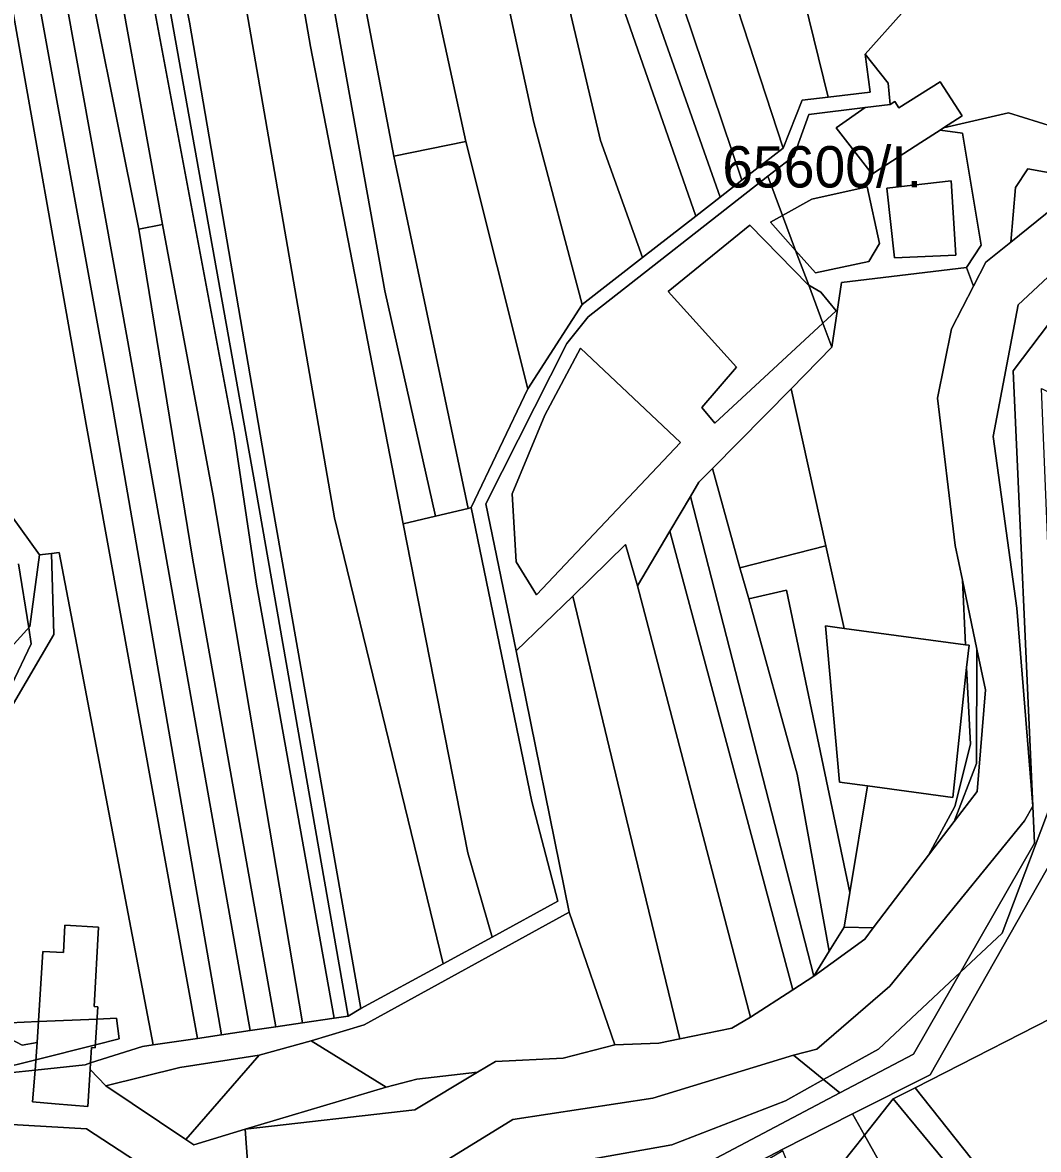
# Model space of a CAD drawing. Extents: x -502026 to -497664, y -1143484 to -1138019.
# Drawn here: x -499256.7 to -499060, y -1140803.4 to -1140585.2 of the extents above; entities that cross this region are included whole.
import ezdxf

# ---------------------------------------------------------------- set-up
doc = ezdxf.new("R2010")
doc.units = 0
for name, color, linetype in [('25', 7, 'Continuous'), ('37', 7, 'Continuous'), ('43', 7, 'Continuous'), ('49', 7, 'Continuous'), ('55', 7, 'Continuous'), ('62', 7, 'Continuous'), ('7', 7, 'Continuous')]:
    doc.layers.add(name, color=color, linetype=linetype)

msp = doc.modelspace()

# ---------------------------------------------------------------- linework, layer by layer
at = {"layer": '25'}
for points in [[(-499046.23, -1140577.07), (-499044.44, -1140577.08), (-499038.84, -1140582.85), (-499039.7, -1140583.71), (-499053.55, -1140597.58), (-499047.59, -1140603.5), (-499051.26, -1140607.19), (-499065.8, -1140602.64), (-499078.37, -1140605.55), (-499074.79, -1140603.26), (-499079.03, -1140596.64), (-499087.03, -1140601.69), (-499087.82, -1140600.44), (-499088.69, -1140601.02), (-499089.09, -1140596.91), (-499093.56, -1140591.31), (-499086.55, -1140583.39), (-499081.37, -1140581.73), (-499069.49, -1140582.91), (-499066.15, -1140581.28), (-499057.06, -1140576.83)], [(-499101.17, -1140686.53), (-499117.79, -1140690.8), (-499123.13, -1140671.52), (-499107.9, -1140656.08)], [(-499097.65, -1140702.49), (-499101.24, -1140702), (-499098.5, -1140732.28), (-499093.13, -1140733.02), (-499096.54, -1140753.64), (-499108.79, -1140695.11), (-499116.1, -1140696.77), (-499117.79, -1140690.8), (-499101.17, -1140686.53)], [(-499096.54, -1140753.64), (-499097.65, -1140760.34), (-499100.52, -1140765.03), (-499106.71, -1140730.74), (-499116.1, -1140696.77), (-499108.79, -1140695.11)]]:
    msp.add_lwpolyline(points, close=True, dxfattribs=at)
at = {"layer": '37'}
for points in [[(-499142.03, -1140783.15), (-499152.04, -1140785.71), (-499165.14, -1140786.36), (-499168.58, -1140788.47), (-499180.35, -1140789.82), (-499186.28, -1140791.32), (-499200.84, -1140782.35), (-499190.58, -1140779.27), (-499150.86, -1140757.46)], [(-499027.17, -1140859.16), (-499039.41, -1140846.13), (-499055.84, -1140826.78), (-499083.85, -1140791.45), (-499051.81, -1140775.1), (-499049.74, -1140796.19), (-499037.55, -1140844.52), (-499031.03, -1140843.42)], [(-499093.69, -1140800.62), (-499104.95, -1140814.88), (-499109.51, -1140803.7), (-499127.89, -1140814.52), (-499149.4, -1140825.3), (-499162.04, -1140835.16), (-499163.96, -1140837.47), (-499165.34, -1140840.32), (-499168.31, -1140844.22), (-499168.31, -1140845.8), (-499179.89, -1140858.73), (-499202.02, -1140881.64), (-499183.66, -1140858.73), (-499166.49, -1140833.21), (-499109.48, -1140803.35), (-499095.98, -1140796.53)], [(-499074.18, -1141090.69), (-499085.94, -1141005.64), (-499111.86, -1140862.39), (-499119.95, -1140833.05), (-499102.17, -1140821.68), (-499104.95, -1140814.88), (-499093.69, -1140800.62), (-499076.01, -1140832.19), (-499068.35, -1140891.61), (-499073.21, -1140904.83), (-499057.38, -1140940.7), (-499042.46, -1140998.31), (-499052.02, -1141001.86), (-499061.09, -1141020.67), (-499058.7, -1141085.37)]]:
    msp.add_lwpolyline(points, close=True, dxfattribs=at)
at = {"layer": '43'}
for points in [[(-499277.06, -1140748.76), (-499311.03, -1140789.86), (-499304.44, -1140768.17), (-499278.12, -1140737.7), (-499277.15, -1140726.28), (-499255.28, -1140702.14), (-499253.41, -1140688.26), (-499251.1, -1140688), (-499250.63, -1140703.66)], [(-499098.45, -1140792.47), (-499169.08, -1140829.79), (-499220.72, -1140841.83), (-499256.21, -1140836.16), (-499277.72, -1140829.32), (-499287.7, -1140819.38), (-499306.66, -1140814.44), (-499352.42, -1140810.64), (-499336.3, -1140807.98), (-499328.65, -1140806.13), (-499324.82, -1140798.07), (-499318.22, -1140791.11), (-499315.45, -1140795.96), (-499302.12, -1140802.04), (-499267.8, -1140798.07), (-499244.32, -1140799.43), (-499230, -1140808.8), (-499223.13, -1140810.06), (-499213.06, -1140806.58), (-499212.54, -1140813.69), (-499178.21, -1140807.73), (-499161.8, -1140797.63), (-499134.65, -1140793.45), (-499107.41, -1140785.15)]]:
    msp.add_lwpolyline(points, close=True, dxfattribs=at)
at = {"layer": '49'}
for points in [[(-499088.69, -1140601.02), (-499093.53, -1140601.61), (-499104.46, -1140602.95), (-499107.34, -1140611.05), (-499112.42, -1140614.89), (-499147.18, -1140642.14), (-499151.34, -1140647.33), (-499167, -1140678.36), (-499161.11, -1140706.87), (-499150.86, -1140757.46), (-499190.58, -1140779.27), (-499200.84, -1140782.35), (-499210.91, -1140785.18), (-499226.23, -1140787.52), (-499240.55, -1140791.12), (-499243.62, -1140787.96), (-499243.54, -1140786.63), (-499233.45, -1140783.49), (-499231.38, -1140783.18), (-499222.82, -1140781.91), (-499218.19, -1140781.23), (-499212.6, -1140780.4), (-499207.66, -1140779.67), (-499202.47, -1140778.9), (-499196.38, -1140778), (-499193.66, -1140777.6), (-499191.2, -1140776.13), (-499175.25, -1140767.44), (-499165.77, -1140762.27), (-499153.04, -1140755.33), (-499158.1, -1140736.04), (-499169.83, -1140679.11), (-499158.84, -1140656.08), (-499148.34, -1140639.76), (-499136.68, -1140630.69), (-499126.34, -1140622.65), (-499121.6, -1140618.96), (-499117.43, -1140615.72), (-499109.46, -1140609.52), (-499105.73, -1140600.19), (-499100.72, -1140599.59), (-499092.59, -1140598.62), (-499093.56, -1140591.31), (-499089.09, -1140596.91)], [(-499075.98, -1140630.21), (-499087.86, -1140630.73), (-499089.39, -1140617.21), (-499076.89, -1140615.85)], [(-499107.02, -1140629.29), (-499109.55, -1140622.53), (-499103.88, -1140619.37), (-499093.18, -1140616.99), (-499090.81, -1140627.99), (-499092.85, -1140631.42), (-499103.15, -1140633.62)], [(-499104.48, -1140636.06), (-499101.74, -1140643.37), (-499122.67, -1140662.76), (-499125.2, -1140659.73), (-499118.48, -1140651.93), (-499131.72, -1140637.28), (-499115.91, -1140624.38), (-499104.62, -1140635.97)], [(-499107.02, -1140629.29), (-499111.9, -1140623.84), (-499109.55, -1140622.53)], [(-499101.74, -1140643.37), (-499104.48, -1140636.06), (-499102.16, -1140637.4), (-499099.19, -1140641.01)], [(-499129.28, -1140666.5), (-499157.22, -1140695.98), (-499161.12, -1140689.62), (-499161.88, -1140676.45), (-499155.56, -1140661.22), (-499148.66, -1140648.25)]]:
    msp.add_lwpolyline(points, close=True, dxfattribs=at)
for points in [[(-499213.06, -1140806.58), (-499213.58, -1140799.48), (-499180.73, -1140795.76), (-499168.58, -1140788.47), (-499165.14, -1140786.36), (-499152.04, -1140785.71), (-499142.03, -1140783.15), (-499133.53, -1140782.8), (-499129.46, -1140781.97), (-499119.38, -1140779.92), (-499115.76, -1140777.81), (-499107.58, -1140772.51), (-499103.47, -1140769.84), (-499093.62, -1140762.66), (-499091.98, -1140760.5), (-499081.3, -1140746.44), (-499076.35, -1140739.92), (-499071.9, -1140734.07), (-499070.28, -1140714.4), (-499071.93, -1140706.5), (-499074.73, -1140693.14), (-499076.12, -1140686.47), (-499079.52, -1140657.94), (-499076.87, -1140644.51), (-499072.58, -1140636.22), (-499070.17, -1140631.57), (-499065.36, -1140627.7), (-499056.95, -1140620.92)], [(-499052.36, -1140629.03), (-499063.95, -1140639.83), (-499068.76, -1140665.31), (-499064.16, -1140698.58), (-499061.08, -1140736.96), (-499062.7, -1140739.8), (-499088.79, -1140771.82), (-499102.91, -1140783.99), (-499107.41, -1140785.15), (-499134.65, -1140793.45), (-499161.8, -1140797.63), (-499178.21, -1140807.73)], [(-499264.63, -1140672.68), (-499253.41, -1140688.26), (-499255.28, -1140702.14), (-499277.15, -1140726.28)], [(-499299.02, -1140792.7), (-499254.28, -1140788.04), (-499254.78, -1140794.22), (-499250.4, -1140794.57), (-499244.07, -1140795.09), (-499243.62, -1140787.96), (-499240.55, -1140791.12), (-499225.11, -1140801.48), (-499223.53, -1140802.54), (-499213.58, -1140799.48), (-499213.06, -1140806.58)], [(-499230, -1140808.8), (-499244.32, -1140799.43), (-499267.8, -1140798.07)]]:
    msp.add_lwpolyline(points, dxfattribs=at)
at = {"layer": '55'}
for points in [[(-499078.37, -1140605.55), (-499079.04, -1140605.98), (-499082.8, -1140608.39), (-499091.53, -1140614.08), (-499092.22, -1140614.53), (-499099.16, -1140605.57), (-499093.53, -1140601.61), (-499088.69, -1140601.02), (-499087.82, -1140600.44), (-499087.03, -1140601.69), (-499079.03, -1140596.64), (-499074.79, -1140603.26)], [(-499079.04, -1140605.98), (-499074.68, -1140606.61), (-499071.1, -1140628.29), (-499073.93, -1140632.6), (-499098.12, -1140635.51), (-499099.98, -1140648.05), (-499101.74, -1140643.37), (-499099.19, -1140641.01), (-499102.16, -1140637.4), (-499104.48, -1140636.06), (-499107.02, -1140629.29), (-499103.15, -1140633.62), (-499092.85, -1140631.42), (-499090.81, -1140627.99), (-499093.18, -1140616.99), (-499103.88, -1140619.37), (-499109.55, -1140622.53), (-499112.42, -1140614.89), (-499107.34, -1140611.05), (-499104.46, -1140602.95), (-499093.53, -1140601.61), (-499099.16, -1140605.57), (-499092.22, -1140614.53), (-499091.53, -1140614.08), (-499082.8, -1140608.39)], [(-499051.26, -1140607.19), (-499047.02, -1140608.51), (-499038.79, -1140615.12), (-499050.8, -1140618.95), (-499053.11, -1140615.08), (-499062.07, -1140613.51), (-499064.46, -1140617.09), (-499065.36, -1140627.7), (-499070.17, -1140631.57), (-499072.58, -1140636.22), (-499073.93, -1140632.6), (-499071.1, -1140628.29), (-499074.68, -1140606.61), (-499079.04, -1140605.98), (-499078.37, -1140605.55), (-499065.8, -1140602.64)], [(-499050.8, -1140618.95), (-499056.95, -1140620.92), (-499065.36, -1140627.7), (-499064.46, -1140617.09), (-499062.07, -1140613.51), (-499053.11, -1140615.08)], [(-499109.55, -1140622.53), (-499111.9, -1140623.84), (-499107.02, -1140629.29), (-499104.48, -1140636.06), (-499104.62, -1140635.97), (-499115.91, -1140624.38), (-499131.72, -1140637.28), (-499118.48, -1140651.93), (-499125.2, -1140659.73), (-499122.67, -1140662.76), (-499101.74, -1140643.37), (-499099.98, -1140648.05), (-499107.9, -1140656.08), (-499123.13, -1140671.52), (-499125.73, -1140674.16), (-499127.4, -1140676.97), (-499131.38, -1140683.68), (-499137.65, -1140694.23), (-499139.97, -1140686.27), (-499150.13, -1140696.23), (-499161.11, -1140706.87), (-499167, -1140678.36), (-499151.34, -1140647.33), (-499147.18, -1140642.14), (-499112.42, -1140614.89)], [(-499075.98, -1140630.21), (-499076.89, -1140615.85), (-499089.39, -1140617.21), (-499087.86, -1140630.73)], [(-499061.08, -1140736.96), (-499064.16, -1140698.58), (-499068.76, -1140665.31), (-499063.95, -1140639.83), (-499052.36, -1140629.03), (-499045.77, -1140627.37), (-499064.92, -1140652.65)], [(-499072.58, -1140636.22), (-499076.87, -1140644.51), (-499079.52, -1140657.94), (-499076.12, -1140686.47), (-499074.73, -1140693.14), (-499074.12, -1140705.68), (-499097.65, -1140702.49), (-499101.17, -1140686.53), (-499107.9, -1140656.08), (-499099.98, -1140648.05), (-499098.12, -1140635.51), (-499073.93, -1140632.6)], [(-499129.28, -1140666.5), (-499148.66, -1140648.25), (-499155.56, -1140661.22), (-499161.88, -1140676.45), (-499161.12, -1140689.62), (-499157.22, -1140695.98)], [(-499020.1, -1140675.56), (-499029, -1140688.61), (-499033.93, -1140693.11), (-499030.81, -1140719.88), (-499035.84, -1140743.39), (-499034.62, -1140755.24), (-499032.97, -1140765.49), (-499051.81, -1140775.1), (-499083.85, -1140791.45), (-499088.14, -1140793.58), (-499093.69, -1140800.62), (-499095.98, -1140796.53), (-499080.97, -1140788.98), (-499055.8, -1140744.6), (-499059.42, -1140656.04)], [(-499231.38, -1140783.18), (-499233.45, -1140783.49), (-499243.54, -1140786.63), (-499243.35, -1140783.68), (-499242.62, -1140783.74), (-499242.09, -1140775.8), (-499242.86, -1140775.72), (-499242.02, -1140760.36), (-499248.5, -1140759.99), (-499248.79, -1140765.28), (-499252.74, -1140765.06), (-499253.84, -1140782.67), (-499256.76, -1140783.21), (-499267.22, -1140777.72), (-499277.06, -1140748.76), (-499250.63, -1140703.66), (-499251.1, -1140688), (-499249.58, -1140687.83), (-499246.17, -1140705.68)], [(-499071.93, -1140706.5), (-499071.99, -1140728.66), (-499076.35, -1140739.92), (-499081.3, -1140746.44), (-499076.18, -1140737), (-499073.19, -1140724.92), (-499073.91, -1140710.05), (-499073.45, -1140705.77), (-499074.12, -1140705.68), (-499074.73, -1140693.14)], [(-499097.65, -1140702.49), (-499074.12, -1140705.68), (-499073.45, -1140705.77), (-499073.91, -1140710.05), (-499076.61, -1140735.28), (-499093.13, -1140733.02), (-499098.5, -1140732.28), (-499101.24, -1140702)], [(-499076.35, -1140739.92), (-499071.99, -1140728.66), (-499071.93, -1140706.5), (-499070.28, -1140714.4), (-499071.9, -1140734.07)], [(-499081.3, -1140746.44), (-499091.98, -1140760.5), (-499097.65, -1140760.34), (-499096.54, -1140753.64), (-499093.13, -1140733.02), (-499076.61, -1140735.28), (-499073.91, -1140710.05), (-499073.19, -1140724.92), (-499076.18, -1140737)], [(-499098.45, -1140792.47), (-499107.41, -1140785.15), (-499102.91, -1140783.99), (-499088.79, -1140771.82), (-499062.7, -1140739.8), (-499061.08, -1140736.96), (-499060.76, -1140744.08), (-499084.18, -1140784.93)], [(-499253.84, -1140782.67), (-499254.28, -1140788.04), (-499299.02, -1140792.7), (-499311.03, -1140789.86), (-499277.06, -1140748.76), (-499267.22, -1140777.72), (-499256.76, -1140783.21)], [(-499243.54, -1140786.63), (-499244.57, -1140787.02), (-499250.02, -1140787.59), (-499254.28, -1140788.04), (-499253.84, -1140782.67), (-499252.74, -1140765.06), (-499248.79, -1140765.28), (-499248.5, -1140759.99), (-499242.02, -1140760.36), (-499242.86, -1140775.72), (-499242.09, -1140775.8), (-499242.62, -1140783.74), (-499243.35, -1140783.68)], [(-499091.98, -1140760.5), (-499093.62, -1140762.66), (-499103.47, -1140769.84), (-499100.52, -1140765.03), (-499097.65, -1140760.34)], [(-499186.28, -1140791.32), (-499213.58, -1140799.48), (-499223.53, -1140802.54), (-499225.11, -1140801.48), (-499210.91, -1140785.18), (-499200.84, -1140782.35)], [(-499225.11, -1140801.48), (-499240.55, -1140791.12), (-499226.23, -1140787.52), (-499210.91, -1140785.18)], [(-499243.62, -1140787.96), (-499244.07, -1140795.09), (-499250.4, -1140794.57), (-499254.78, -1140794.22), (-499254.28, -1140788.04), (-499250.02, -1140787.59), (-499244.57, -1140787.02), (-499243.54, -1140786.63)], [(-499213.58, -1140799.48), (-499186.28, -1140791.32), (-499180.35, -1140789.82), (-499168.58, -1140788.47), (-499180.73, -1140795.76)], [(-499027.17, -1140859.16), (-499026.07, -1140862.91), (-499030.49, -1140860.96), (-499059.43, -1140828.31), (-499088.14, -1140793.58), (-499083.85, -1140791.45), (-499055.84, -1140826.78), (-499039.41, -1140846.13)], [(-499026.07, -1140862.91), (-499025.31, -1140901.92), (-499045.76, -1140905.71), (-499036.36, -1140939.98), (-499029.76, -1140973.78), (-499028.12, -1140987.18), (-499023, -1141004.29), (-499026.05, -1141018.97), (-499027.79, -1141042.52), (-499029.21, -1141087.84), (-499073.37, -1141096.58), (-499074.18, -1141090.69), (-499058.7, -1141085.37), (-499061.09, -1141020.67), (-499052.02, -1141001.86), (-499042.46, -1140998.31), (-499057.38, -1140940.7), (-499073.21, -1140904.83), (-499068.35, -1140891.61), (-499076.01, -1140832.19), (-499093.69, -1140800.62), (-499088.14, -1140793.58), (-499059.43, -1140828.31), (-499030.49, -1140860.96)]]:
    msp.add_lwpolyline(points, close=True, dxfattribs=at)
for points in [[(-499169.08, -1140829.79), (-499098.45, -1140792.47), (-499084.18, -1140784.93), (-499060.76, -1140744.08), (-499061.08, -1140736.96), (-499064.92, -1140652.65), (-499045.77, -1140627.37)], [(-499055.8, -1140744.6), (-499080.97, -1140788.98), (-499095.98, -1140796.53), (-499109.48, -1140803.35), (-499166.49, -1140833.21)]]:
    msp.add_lwpolyline(points, dxfattribs=at)
at = {"layer": '62'}
for points in [[(-499266.5, -1140729.5), (-499255, -1140705.5), (-499255.5, -1140702.38), (-499257.5, -1140690)], [(-499257.5, -1140690), (-499255.5, -1140702.38), (-499255, -1140705.5), (-499266.5, -1140729.5)], [(-499178.5, -1140811), (-499131, -1140802.5), (-499109, -1140794), (-499101.61, -1140789.89), (-499091, -1140784), (-499075.1, -1140769.09), (-499067, -1140761.5), (-499056.27, -1140733.02)], [(-499056.27, -1140733.02), (-499067, -1140761.5), (-499075.1, -1140769.09), (-499091, -1140784), (-499101.61, -1140789.89), (-499109, -1140794), (-499131, -1140802.5), (-499178.5, -1140811)], [(-499262, -1140788), (-499254.12, -1140786.03), (-499242.58, -1140783.14), (-499238, -1140782), (-499238.5, -1140778), (-499242.25, -1140778.16), (-499253.59, -1140778.64), (-499262, -1140779)], [(-499262, -1140779), (-499253.59, -1140778.64), (-499242.25, -1140778.16), (-499238.5, -1140778), (-499238, -1140782), (-499242.58, -1140783.14), (-499254.12, -1140786.03), (-499262, -1140788)]]:
    msp.add_lwpolyline(points, dxfattribs=at)
at = {"layer": '7'}
for points in [[(-499086.55, -1140583.39), (-499093.56, -1140591.31), (-499092.59, -1140598.62), (-499100.72, -1140599.59), (-499129.23, -1140483.41), (-499114.75, -1140475.43), (-499108.4, -1140504.75), (-499093.32, -1140556.79)], [(-499100.72, -1140599.59), (-499105.73, -1140600.19), (-499109.46, -1140609.52), (-499125.99, -1140558.72), (-499133.51, -1140529.07), (-499142.57, -1140490.76), (-499129.23, -1140483.41)], [(-499109.46, -1140609.52), (-499117.43, -1140615.72), (-499130.6, -1140576.56), (-499141.21, -1140536.53), (-499150.34, -1140495.5), (-499142.57, -1140490.76), (-499133.51, -1140529.07), (-499125.99, -1140558.72)], [(-499117.43, -1140615.72), (-499121.6, -1140618.96), (-499136.08, -1140577.94), (-499147.66, -1140536.99), (-499155.56, -1140498.69), (-499150.34, -1140495.5), (-499141.21, -1140536.53), (-499130.6, -1140576.56)], [(-499121.6, -1140618.96), (-499126.34, -1140622.65), (-499140.99, -1140580.59), (-499154.21, -1140533), (-499159.55, -1140503.7), (-499159.98, -1140501.39), (-499155.56, -1140498.69), (-499147.66, -1140536.99), (-499136.08, -1140577.94)], [(-499126.34, -1140622.65), (-499136.68, -1140630.69), (-499144.8, -1140608), (-499168.02, -1140509.43), (-499159.55, -1140503.7), (-499154.21, -1140533), (-499140.99, -1140580.59)], [(-499168.02, -1140509.43), (-499144.8, -1140608), (-499136.68, -1140630.69), (-499148.34, -1140639.76), (-499157.71, -1140604.5), (-499177.54, -1140513.37), (-499170.64, -1140508.17)], [(-499148.34, -1140639.76), (-499158.84, -1140656.08), (-499170.88, -1140608.2), (-499189.52, -1140522.4), (-499177.54, -1140513.37), (-499157.71, -1140604.5)], [(-499170.88, -1140608.2), (-499184.82, -1140611.02), (-499200.19, -1140530.44), (-499189.52, -1140522.4)], [(-499184.82, -1140611.02), (-499170.43, -1140679.25), (-499176.76, -1140680.77), (-499186.58, -1140637.13), (-499205.05, -1140534.1), (-499200.19, -1140530.44)], [(-499176.76, -1140680.77), (-499182.99, -1140682.26), (-499200.94, -1140589.81), (-499209.99, -1140537.82), (-499205.05, -1140534.1), (-499186.58, -1140637.13)], [(-499182.99, -1140682.26), (-499170.46, -1140745.98), (-499165.77, -1140762.27), (-499175.25, -1140767.44), (-499196.33, -1140681.1), (-499214.16, -1140577.79), (-499220.46, -1140545.72), (-499209.99, -1140537.82), (-499200.94, -1140589.81)], [(-499175.25, -1140767.44), (-499191.2, -1140776.13), (-499208.46, -1140678.05), (-499224.38, -1140585.07), (-499230.66, -1140553.16), (-499220.46, -1140545.72), (-499214.16, -1140577.79), (-499196.33, -1140681.1)], [(-499193.66, -1140777.6), (-499196.38, -1140778), (-499211.37, -1140693.94), (-499215.73, -1140664.96), (-499236.04, -1140556.46), (-499233.16, -1140554.69), (-499212.01, -1140673.04)], [(-499191.2, -1140776.13), (-499193.66, -1140777.6), (-499212.01, -1140673.04), (-499233.16, -1140554.69), (-499230.66, -1140553.16), (-499224.38, -1140585.07), (-499208.46, -1140678.05)], [(-499196.38, -1140778), (-499202.47, -1140778.9), (-499219.79, -1140676.84), (-499229.59, -1140624.31), (-499241.25, -1140559.66), (-499236.04, -1140556.46), (-499215.73, -1140664.96), (-499211.37, -1140693.94)], [(-499229.59, -1140624.31), (-499234.17, -1140625.16), (-499246.66, -1140562.99), (-499241.25, -1140559.66)], [(-499234.17, -1140625.16), (-499223.77, -1140688.89), (-499207.66, -1140779.67), (-499212.6, -1140780.4), (-499236.3, -1140647.03), (-499251.02, -1140565.67), (-499246.66, -1140562.99)], [(-499212.6, -1140780.4), (-499218.19, -1140781.23), (-499239.42, -1140658.77), (-499255.78, -1140568.6), (-499251.02, -1140565.67), (-499236.3, -1140647.03)], [(-499218.19, -1140781.23), (-499222.82, -1140781.91), (-499244.36, -1140663), (-499260.6, -1140571.56), (-499255.78, -1140568.6), (-499239.42, -1140658.77)], [(-499222.82, -1140781.91), (-499231.38, -1140783.18), (-499246.17, -1140705.68), (-499249.58, -1140687.83), (-499251.1, -1140688), (-499253.41, -1140688.26), (-499264.63, -1140672.68), (-499268.97, -1140641.12), (-499281.18, -1140586.94), (-499260.6, -1140571.56), (-499244.36, -1140663)], [(-499158.84, -1140656.08), (-499169.83, -1140679.11), (-499170.43, -1140679.25), (-499184.82, -1140611.02), (-499170.88, -1140608.2)], [(-499202.47, -1140778.9), (-499207.66, -1140779.67), (-499223.77, -1140688.89), (-499234.17, -1140625.16), (-499229.59, -1140624.31), (-499219.79, -1140676.84)], [(-499117.79, -1140690.8), (-499116.1, -1140696.77), (-499106.71, -1140730.74), (-499100.52, -1140765.03), (-499103.47, -1140769.84), (-499127.4, -1140676.97), (-499125.73, -1140674.16), (-499123.13, -1140671.52)], [(-499103.47, -1140769.84), (-499107.58, -1140772.51), (-499131.38, -1140683.68), (-499127.4, -1140676.97)], [(-499165.77, -1140762.27), (-499170.46, -1140745.98), (-499182.99, -1140682.26), (-499176.76, -1140680.77), (-499170.43, -1140679.25), (-499169.83, -1140679.11), (-499158.1, -1140736.04), (-499153.04, -1140755.33)], [(-499107.58, -1140772.51), (-499115.76, -1140777.81), (-499137.65, -1140694.23), (-499131.38, -1140683.68)], [(-499137.65, -1140694.23), (-499115.76, -1140777.81), (-499119.38, -1140779.92), (-499129.46, -1140781.97), (-499139.77, -1140739.43), (-499150.13, -1140696.23), (-499139.97, -1140686.27)], [(-499129.46, -1140781.97), (-499133.53, -1140782.8), (-499142.03, -1140783.15), (-499150.86, -1140757.46), (-499161.11, -1140706.87), (-499150.13, -1140696.23), (-499139.77, -1140739.43)]]:
    msp.add_lwpolyline(points, close=True, dxfattribs=at)

# ---------------------------------------------------------------- texts
at = {"layer": '62'}
msp.add_text('65600/I.', height=8, dxfattribs=at).set_placement((-499121.21, -1140617.11))

doc.saveas('drawing.dxf')
